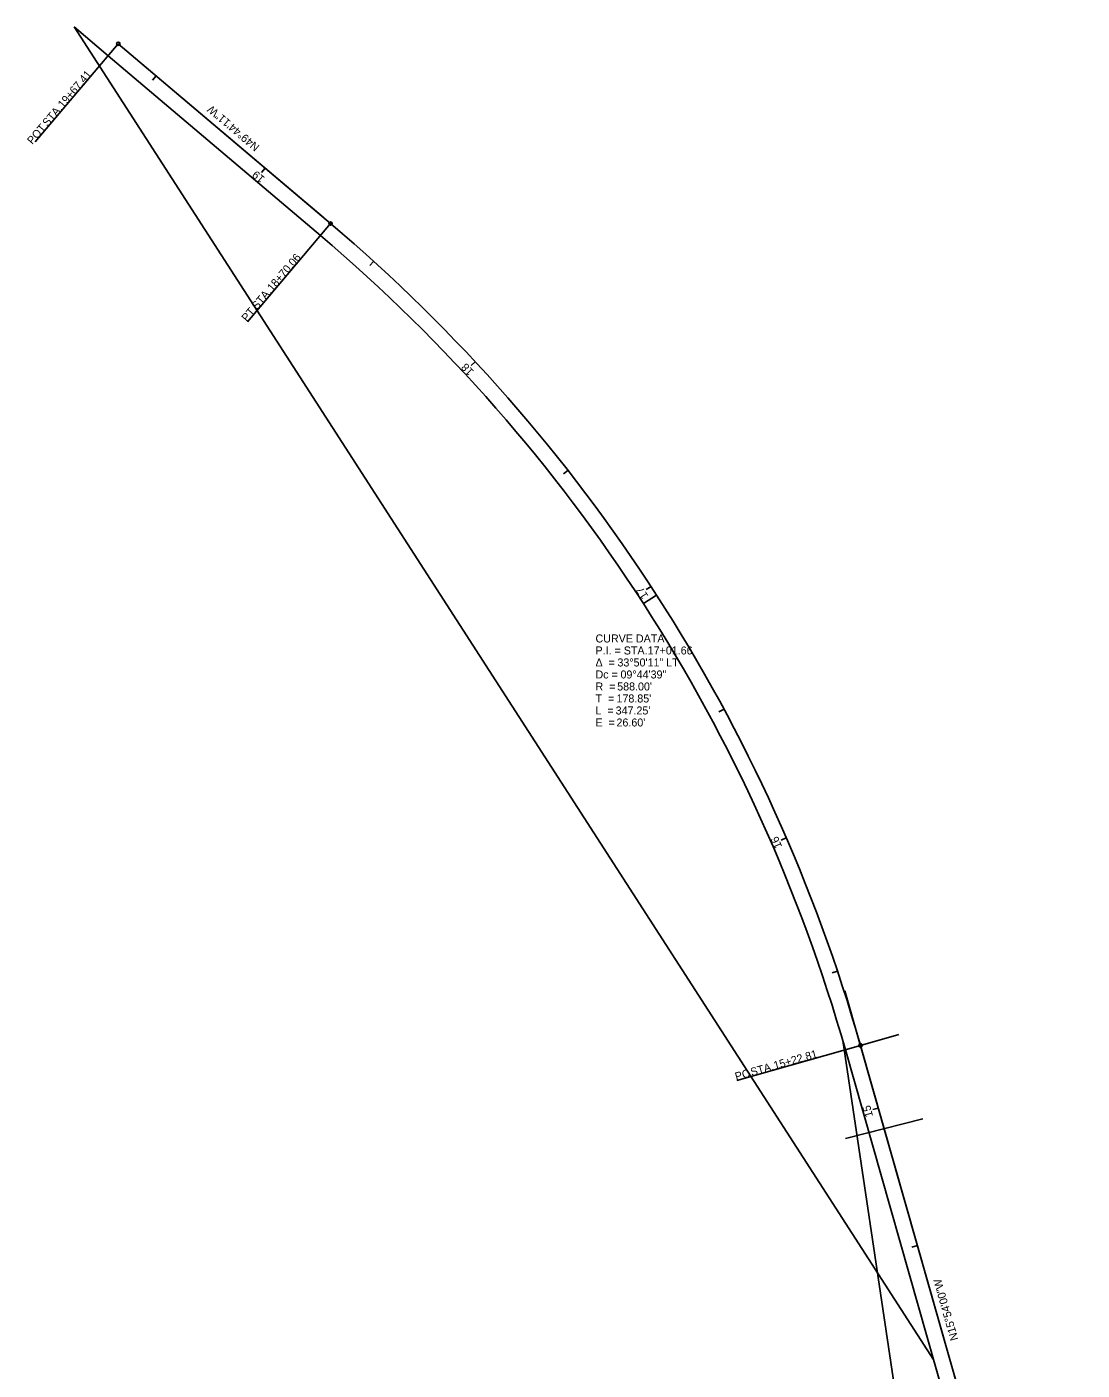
# Model space of a CAD drawing. Extents: x 215740 to 216118, y 335523 to 336438.
# Drawn here: x 215740.1 to 216109.5, y 335967.6 to 336437.7 of the extents above; entities that cross this region are included whole.
import ezdxf

# ---------------------------------------------------------------- set-up
doc = ezdxf.new("R2010")
doc.units = 0
doc.layers.add('DV_X_Property_Line', color=7, linetype='Continuous')
doc.layers.add('RW_X_Fee_RW', color=7, linetype='Continuous')

msp = doc.modelspace()

# ---------------------------------------------------------------- linework, layer by layer
at = {"layer": 'DV_X_Property_Line'}
for p, q in [((215768.61, 336427.54), (215756.67, 336437.66)), ((215756.67, 336437.66), (216057.59, 335971.04)), ((215772.16, 336431.74), (215743.08, 336397.4)), ((215842.89, 336364.63), (215768.61, 336427.54)), ((215785.45, 336420.49), (215784.15, 336418.96)), ((215823.6, 336388.18), (215822.31, 336386.65)), ((215846.45, 336368.82), (215817.37, 336334.48)), ((215861.53, 336355.6), (215860.19, 336354.12)), ((215897.09, 336320.47), (215895.62, 336319.11)), ((215929.53, 336282.45), (215927.96, 336281.22)), ((215958.63, 336241.81), (215956.96, 336240.71)), ((215960.57, 336238.81), (215955.95, 336235.83)), ((215984.17, 336198.84), (215982.41, 336197.89)), ((216005.97, 336153.86), (216004.14, 336153.06)), ((216023.87, 336107.19), (216021.98, 336106.55)), ((216031.93, 336081.22), (216045.39, 336085.06)), ((216031.93, 336081.22), (215988.65, 336068.89)), ((216025.7, 336082.97), (216025.7, 336082.97)), ((216109.52, 335522.94), (216025.7, 336082.97)), ((216079.25, 335895.01), (216026.64, 336079.71)), ((216038.17, 336059.28), (216036.25, 336058.74)), ((216026.66, 336048.57), (216053.7, 336055.55)), ((216051.87, 336011.2), (216049.95, 336010.65)), ((216057.59, 335971.04), (216057.59, 335971.04))]:
    msp.add_line(p, q, dxfattribs=at)
for centre in [(215772.16, 336431.74), (215846.45, 336368.82), (216031.93, 336081.22)]:
    msp.add_circle(centre, 0.6, dxfattribs=at)
msp.add_arc((215466.42, 335920.13), 582.5, 15.89995, 49.7364, dxfattribs=at)
at = {"layer": 'RW_X_Fee_RW'}
for p, q in [((215843.83, 336371.04), (215772.16, 336431.74)), ((215846.45, 336368.82), (215772.16, 336431.74)), ((216088.51, 335882.59), (216026.49, 336100.3)), ((216084.54, 335896.51), (216031.93, 336081.22))]:
    msp.add_line(p, q, dxfattribs=at)
msp.add_arc((215466.42, 335920.13), 588, 15.89995, 49.7364, dxfattribs=at)
msp.add_arc((215466.42, 335920.13), 588, 15.89995, 49.7364, dxfattribs=at)

# ---------------------------------------------------------------- texts
at = {"layer": 'DV_X_Property_Line'}
for s, rotation, p in [('19+67.41', 49.7364, (215752.85, 336409)), (' STA. ', 49.7364, (215746.74, 336401.79)), ('N49°44\'11"W', 139.7364, (215821.81, 336395.99)), ('POT', 49.7364, (215742.09, 336396.3)), ('19', 139.7364, (215823.66, 336384.85)), ('18+70.06', 49.7364, (215826.1, 336344.86)), (' STA. ', 49.7364, (215819.99, 336337.65)), ('PT', 49.7364, (215817.14, 336334.28)), ('18', 132.91, (215896.77, 336317.15)), ('17', 123.1658, (215957.8, 336238.51)), ('16', 113.4216, (216004.57, 336150.81)), ('15+22.81', 15.9, (216001.96, 336072.73)), (' STA. ', 15.9, (215992.87, 336070.14)), ('PC', 15.9, (215988.46, 336068.88)), ('15', 105.9, (216036.37, 336056.5)), ('N15°54\'00"W', 105.9, (216066.22, 335978.34))]:
    msp.add_text(s, height=2.8, rotation=rotation, dxfattribs=at).set_placement(p)
for s, p in [('CURVE DATA', (215939.19, 336222.22)), ('P.I. = STA. ', (215939.19, 336218.02)), ('17+01.66', (215957.45, 336218.02)), ('Δ  = ', (215939.19, 336213.82)), ('33°50\'11" LT', (215946.86, 336213.82)), ('Dc = ', (215939.19, 336209.62)), ('09°44\'39"', (215947.93, 336209.62)), ('R  = ', (215939.19, 336205.42)), ("588.00'", (215946.77, 336205.42)), ('T  = ', (215939.19, 336201.22)), ("178.85'", (215946.53, 336201.22)), ('L  = ', (215939.19, 336197.02)), ("347.25'", (215946.23, 336197.02)), ('E  = ', (215939.19, 336192.82)), ("26.60'", (215946.53, 336192.82))]:
    msp.add_text(s, height=2.8, dxfattribs=at).set_placement(p)

doc.saveas('drawing.dxf')
